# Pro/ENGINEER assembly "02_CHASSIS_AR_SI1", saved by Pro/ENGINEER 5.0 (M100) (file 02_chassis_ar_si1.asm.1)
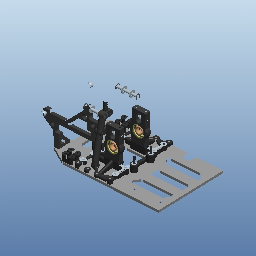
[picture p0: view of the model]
Units: millimeter Newton Second (mmNs); MM, TONNE, HOURS

Other components: CHASSIS_AR-A0, 80650901-PLAQUE_SUP_TR-AR_SI1, 80134000-SUP_DIFF_SI1, 80134000-SUP_DIFF_SI1, 80461501-POTENCE_BASC_AR_SI1, AXE_BASCULEUR_SI1, 80463400-RENF_SUP_CELL_AR_SI1, EQU_RENF_AR_SI1, 80164501-CHAPE_ANCR_AMORT_H_SI1, AXE_AMORT_SI1, 02-ROTULE_STD_SI1, 02-ROTULE_STD_SI1, E-ROTULE_BOULON-M4_SI1, E-ROTULE_BOULON-M4_SI1, E2-ROTULE_BOULON-M4, E2-ROTULE_BOULON-M4, AXE_BASCULEUR_SI1, ROT_STD-A0, ROT_STD-A0

Other named items: 80650901-PLAQUE_SUP_TR-AR_01, 80461501-POTENCE_BASC_AR_01, 80134000-SUP_DIFF_01, 80164501-CHAPE_ANCR_AMORT_H_01, AXE_AMORT_01, 02-ROTULE_STD_V11, E-ROTULE_BOULON-M4, AXE_BASCULEUR, A-DROITE, A-DESSUS, A-FACE, A-R0, ACS0, ACS2, ACS3, ACS4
